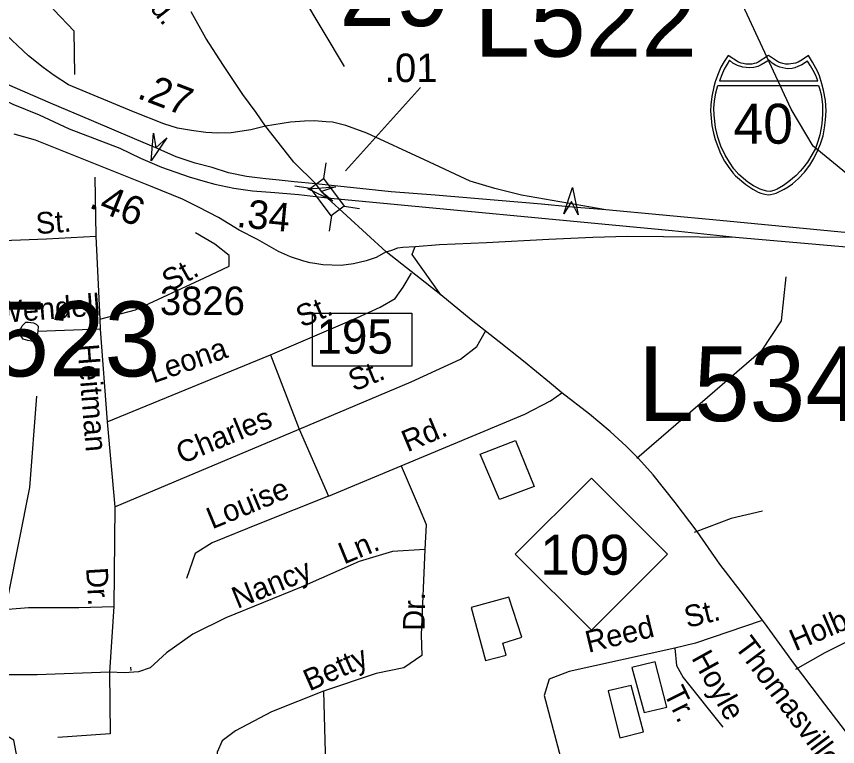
# Model space of a CAD drawing. Extents: x 1553981 to 1780076, y 812965 to 996873.
# Drawn here: x 1634453.2 to 1634902.9, y 846130.3 to 846530.3 of the extents above; entities that cross this region are included whole.
import ezdxf

# ---------------------------------------------------------------- set-up
doc = ezdxf.new("R2010")
doc.units = 0
for name, color, linetype in [('Exist Civil Correctional or Penal Institution CELL', 7, 'Continuous'), ('Exist Civil NCDOT Division Office Label', 7, 'Continuous'), ('Exist Cultural Church with Cemetery CELL', 7, 'Continuous'), ('Exist Cultural Warehouse Building Footprint', 7, 'Continuous'), ('Exist Geographical Mountain Summit Label', 7, 'Continuous'), ('Exist Hydrographic Creek Single Shore', 7, 'Continuous'), ('Exist Road Non-System Type 51 Label', 7, 'Continuous'), ('Exist Road Primary Interstate Divided Center Attributed', 7, 'Continuous'), ('Exist Road Primary Interstate Ramp 1 Lane Attributed', 7, 'Continuous'), ('Exist Road Primary Interstate Service Attributed', 7, 'Continuous'), ('Exist Road Primary Interstate Shield CELL', 7, 'Continuous'), ('Exist Road Primary Interstate Structure Cantilever Sign Number Label', 7, 'Continuous'), ('Exist Road Primary NC Attributed', 7, 'Continuous'), ('Exist Road Primary NC Label', 7, 'Continuous'), ('Exist Road Primary NC Service Mileage Hundredths English Label', 7, 'Continuous'), ('Exist Road Primary NC Shield Number Label', 7, 'Continuous'), ('Exist Road Primary NC Structure Standard Bridge CELL', 7, 'Continuous'), ('Exist Road Secondary Structure Standard Bridge Attributed CELL', 7, 'Continuous'), ('Exist Road Secondary Structure Standard Bridge Number Label', 7, 'Continuous'), ('Exist Road Secondary Type 51 Attributed', 7, 'Continuous'), ('Exist Road Secondary Type 51 Number Label', 7, 'Continuous'), ('Map Preparation Border Antique Large Shape', 7, 'Continuous'), ('Map Preparation Border County Name Lower Right Label', 7, 'Continuous'), ('Map Preparation Border Division and District Label', 7, 'Continuous')]:
    doc.layers.add(name, color=color, linetype=linetype)

msp = doc.modelspace()

# ---------------------------------------------------------------- linework, layer by layer
at = {"layer": 'Exist Civil Correctional or Penal Institution CELL'}
msp.add_lwpolyline([(1634615.3, 846367.85), (1634669.67, 846367.85), (1634669.67, 846338.69), (1634615.3, 846338.69)], close=True, dxfattribs=at)
at = {"layer": 'Exist Cultural Church with Cemetery CELL'}
for points in [[(1634535.67, 846463.73), (1634527.02, 846451.19), (1634528.24, 846466.38), (1634529.57, 846458.37)], [(1634752.88, 846422.12), (1634757.64, 846436.6), (1634760.75, 846421.68), (1634757.21, 846428.99)]]:
    msp.add_lwpolyline(points, close=True, dxfattribs=at)
at = {"layer": 'Exist Cultural Warehouse Building Footprint'}
for points in [[(1634726.5, 846297.94), (1634736.65, 846272.88), (1634717.7, 846265.77), (1634707.21, 846290.49)], [(1634702.14, 846206.5), (1634710.13, 846177.55), (1634721.43, 846180.43), (1634719.48, 846186.91), (1634729.88, 846190.25), (1634722.78, 846212.26)], [(1634790.11, 846173.66), (1634796.88, 846148.94), (1634809.4, 846151.98), (1634802.97, 846176.7)], [(1634777.25, 846160.79), (1634783.68, 846135.05), (1634796.54, 846138.44), (1634789.77, 846163.84)]]:
    msp.add_lwpolyline(points, close=True, dxfattribs=at)
at = {"layer": 'Exist Hydrographic Creek Single Shore'}
for points in [[(1635251.23, 845900.49), (1635241.98, 845905.61), (1635222.36, 845924.47), (1635148.73, 846037.17), (1635133.36, 846064.15), (1635107.11, 846126.24), (1635100.35, 846173.96), (1635092.23, 846190.95), (1635059.23, 846226.51), (1635014.48, 846310.71), (1634938.4, 846360.17), (1634946.3, 846370.23), (1634946.3, 846412.62), (1634889.57, 846459.33), (1634877.36, 846479.45), (1634841.23, 846557.55), (1634830.22, 846595.11), (1634817.1, 846624.51), (1634780.1, 846674.92), (1634763.85, 846710.53), (1634754.1, 846766.12)], [(1634456.59, 846108.66), (1634451.72, 846133.8), (1634448.6, 846135.9), (1634447.73, 846148.65), (1634443.6, 846160.22), (1634442.84, 846184.03), (1634460.59, 846272.3), (1634464.35, 846322.29)]]:
    msp.add_lwpolyline(points, dxfattribs=at)
at = {"layer": 'Exist Road Primary Interstate Divided Center Attributed'}
for points in [[(1635310.9, 846514.99), (1635297.81, 846505.94), (1635206.93, 846450.34), (1635199, 846446.14), (1635187.26, 846439.53), (1635181.99, 846437), (1635165.26, 846429.66), (1635149.65, 846423.53), (1635130.45, 846416.93), (1635118.31, 846413.99), (1635103.77, 846410.13), (1635090.7, 846407.43), (1635083.37, 846406.49), (1635071.95, 846405.37), (1635060.1, 846403.72), (1635032.42, 846402.32), (1634978.81, 846405.12), (1634940.93, 846408.59), (1634838.36, 846418.57), (1634775.88, 846424.31)], [(1634617.18, 846438.56), (1634605.25, 846439.73), (1634597.1, 846440.6), (1634589.71, 846441.31), (1634583.63, 846442.13), (1634579.27, 846442.71), (1634569.36, 846444.65), (1634560.42, 846447.59), (1634551.11, 846449.92), (1634540.63, 846453.41), (1634529.57, 846458.37), (1634517.93, 846463.32), (1634494.36, 846473.22), (1634471.94, 846482.83), (1634448.37, 846493.02), (1634430.55, 846500.64), (1634404.55, 846511.95)], [(1634397.6, 846506.78), (1634417.39, 846497.59), (1634432.82, 846490.95), (1634451.23, 846482.23), (1634465.66, 846476.41), (1634482.13, 846468.77), (1634509.78, 846458.07), (1634521.17, 846452.72), (1634532.58, 846447.66), (1634547.88, 846442.39), (1634556.65, 846439.8), (1634561.82, 846438.51), (1634572.34, 846436.18), (1634582.52, 846434.73), (1634594.77, 846433.9), (1634607.87, 846432.74), (1634623.29, 846430.99)], [(1634847.02, 846409.33), (1634974.81, 846398.32), (1635004.81, 846395.26), (1635020.95, 846394.19), (1635051.03, 846394.59), (1635057.62, 846395.16), (1635069.56, 846395.12), (1635087.17, 846396.16), (1635103.77, 846398.66), (1635118.98, 846401.86), (1635136.98, 846406.26), (1635163.19, 846414.79), (1635185.2, 846424.03), (1635207.67, 846435.53), (1635224.87, 846445.4), (1635279.89, 846479.71), (1635322.1, 846505.59)], [(1634775.88, 846424.31), (1634755.48, 846426.05), (1634740.82, 846427.53), (1634682.48, 846432.46), (1634658.47, 846434.31), (1634617.18, 846438.56)], [(1634623.29, 846430.99), (1634812.21, 846412.96), (1634847.02, 846409.33)]]:
    msp.add_lwpolyline(points, dxfattribs=at)
at = {"layer": 'Exist Road Primary Interstate Ramp 1 Lane Attributed'}
for points in [[(1634775.88, 846424.31), (1634729.86, 846432.48), (1634715.22, 846436.14), (1634701.65, 846440.12), (1634676.64, 846451.73), (1634645.01, 846466.29), (1634633.59, 846470.6), (1634626.28, 846472.33), (1634622.77, 846472.65), (1634616.2, 846473.18), (1634610.98, 846472.97), (1634603.23, 846472.43), (1634589.61, 846470.21)], [(1634671.56, 846404.33), (1634684.92, 846405.34), (1634710.64, 846406.42), (1634744.83, 846408.25), (1634768.79, 846409.43), (1634787.74, 846409.97), (1634847.02, 846409.33)], [(1634655.67, 846401.36), (1634658.74, 846402.33), (1634662.08, 846403.51), (1634664.77, 846403.94), (1634671.56, 846404.33)], [(1634685.55, 846377.78), (1634669.94, 846399.96), (1634670.69, 846401.9), (1634671.56, 846404.33)]]:
    msp.add_lwpolyline(points, dxfattribs=at)
at = {"layer": 'Exist Road Primary Interstate Service Attributed'}
for points in [[(1634589.61, 846470.21), (1634581.67, 846468.28), (1634570.82, 846466.51), (1634563.44, 846466.35), (1634556.92, 846466.67), (1634549.07, 846467.85), (1634541.34, 846469.07), (1634533.95, 846471.57), (1634517.37, 846477.97), (1634481.76, 846492.89), (1634473.95, 846497.95), (1634467.81, 846502.26), (1634459.84, 846508.82), (1634444.61, 846522.93), (1634432.17, 846532.73)], [(1634655.67, 846401.36), (1634650.23, 846398.24), (1634644.77, 846396.51), (1634637.82, 846394.74), (1634630.98, 846393.82), (1634620.94, 846394.25), (1634616.64, 846395.03), (1634614.1, 846395.38), (1634610.54, 846396.25), (1634603.22, 846398.69), (1634596.71, 846401.54), (1634585.14, 846408.09), (1634575.18, 846413.29), (1634563.92, 846420.1), (1634552.99, 846425.91), (1634544.19, 846430.16), (1634526.66, 846437.33), (1634485.63, 846453.8), (1634463.75, 846462.47), (1634452.08, 846465.85)]]:
    msp.add_lwpolyline(points, dxfattribs=at)
at = {"layer": 'Exist Road Primary Interstate Shield CELL'}
for points in [[(1634865, 846432.63), (1634866.18, 846432.74), (1634867.78, 846433.05), (1634869.32, 846433.56), (1634871.09, 846434.34), (1634873.69, 846435.78), (1634875.79, 846437.01), (1634878.2, 846438.64), (1634881.47, 846441.6), (1634884.72, 846445.03), (1634887.6, 846448.91), (1634889.88, 846452.53), (1634891.89, 846456.68), (1634893.57, 846460.54), (1634894.9, 846464.96), (1634895.78, 846469.24), (1634896.23, 846473.7), (1634896.53, 846478.65), (1634896.19, 846484.21), (1634895.22, 846489.91), (1634894.31, 846493.45), (1634892.94, 846497.7), (1634891.81, 846500.4), (1634889.21, 846505.21), (1634886.86, 846508.91), (1634883.46, 846506.51), (1634881.24, 846505.33), (1634879.88, 846504.72), (1634878.49, 846504.45), (1634875.93, 846504.14), (1634874.32, 846504.21), (1634872.82, 846504.55), (1634871.56, 846504.83), (1634870.53, 846505.33), (1634865, 846508.91), (1634859.46, 846505.33), (1634858.3, 846504.8), (1634857.12, 846504.55), (1634855.97, 846504.23), (1634854.08, 846504.14), (1634852.63, 846504.19), (1634851.15, 846504.45), (1634849.98, 846504.7), (1634848.66, 846505.33), (1634843.02, 846508.91), (1634840.81, 846505.69), (1634839, 846502.52), (1634837.08, 846498.03), (1634835.89, 846494.55), (1634835.04, 846491.69), (1634833.99, 846486.45), (1634833.45, 846481.88), (1634833.36, 846478.65), (1634833.95, 846470.58), (1634834.83, 846466.29), (1634835.74, 846462.81), (1634838.72, 846455.31), (1634840.96, 846451.11), (1634842.89, 846448.09), (1634845.58, 846444.69), (1634847.05, 846443.07), (1634852.65, 846438.17), (1634856.39, 846435.62), (1634859.38, 846434.01), (1634860.78, 846433.47), (1634862.98, 846432.86)], [(1634843.7, 846506.32), (1634842.32, 846504.2), (1634840.74, 846501.35), (1634839.47, 846498.39), (1634838.17, 846495.12), (1634892.12, 846495.1), (1634890.86, 846497.9), (1634889.52, 846500.72), (1634888.11, 846503.29), (1634886.4, 846505.77), (1634883.37, 846503.87), (1634881.17, 846502.83), (1634879.4, 846502.22), (1634877.9, 846501.88), (1634875.57, 846501.69), (1634874.53, 846501.76), (1634871.29, 846502.49), (1634869.1, 846503.39), (1634867.01, 846504.78), (1634865.32, 846506.37), (1634861.05, 846503.78), (1634859.15, 846502.95), (1634856.97, 846502.39), (1634854.58, 846502.09), (1634850.91, 846502.49), (1634848.02, 846503.49), (1634845.54, 846504.78)], [(1634892.44, 846492.43), (1634893.02, 846490.91), (1634893.81, 846487.53), (1634894.23, 846484.93), (1634894.66, 846481.93), (1634894.51, 846476.79), (1634894.26, 846471.46), (1634893.77, 846468.31), (1634893.12, 846465.44), (1634892.22, 846462.26), (1634890.78, 846458.03), (1634888.79, 846454.45), (1634886.31, 846450.47), (1634883.62, 846446.99), (1634882.45, 846445.54), (1634880.24, 846443.21), (1634876.21, 846439.98), (1634873.27, 846437.78), (1634869.75, 846435.7), (1634867.96, 846434.9), (1634865.88, 846434.47), (1634864.17, 846434.59), (1634862.09, 846435.14), (1634860.41, 846435.6), (1634856.73, 846437.59), (1634853.75, 846439.58), (1634848.78, 846443.66), (1634846.09, 846446.8), (1634843.59, 846450.47), (1634841.35, 846454.23), (1634838.97, 846459.19), (1634837.29, 846464.18), (1634836.06, 846469.56), (1634835.24, 846476.14), (1634835.15, 846480.15), (1634835.39, 846484.01), (1634835.76, 846486.03), (1634836.25, 846488.54), (1634837.23, 846492.41)]]:
    msp.add_lwpolyline(points, close=True, dxfattribs=at)
at = {"layer": 'Exist Road Primary NC Attributed'}
for points in [[(1634623.29, 846430.99), (1634620.28, 846434.49), (1634617.18, 846438.56)], [(1634655.67, 846401.36), (1634623.29, 846430.99)], [(1634685.55, 846377.78), (1634655.67, 846401.36)], [(1634909.53, 846135.59), (1634893.49, 846156.7), (1634879.22, 846175.54), (1634872.55, 846184.7), (1634862.91, 846198.16), (1634850.04, 846215.17), (1634838.33, 846230.26), (1634825.97, 846248.23), (1634813.91, 846263.95), (1634801.8, 846279.24), (1634793.94, 846288.18), (1634787.11, 846294.97), (1634778.41, 846302.99), (1634767.02, 846312.42), (1634751.91, 846324.18), (1634745.05, 846329.72), (1634730.97, 846341.4), (1634717.59, 846352.04), (1634702.18, 846364.11), (1634685.55, 846377.78)]]:
    msp.add_lwpolyline(points, dxfattribs=at)
at = {"layer": 'Exist Road Primary NC Service Mileage Hundredths English Label'}
msp.add_line((1634633.39, 846445.79), (1634674.48, 846491.34), dxfattribs=at)
at = {"layer": 'Exist Road Primary NC Structure Standard Bridge CELL'}
for p, q in [((1634622.56, 846450.08), (1634621.33, 846441.54)), ((1634605.74, 846437.47), (1634614.27, 846436.25)), ((1634632.63, 846426.4), (1634641.16, 846425.18)), ((1634625.72, 846421.23), (1634624.5, 846412.69))]:
    msp.add_line(p, q, dxfattribs=at)
msp.add_lwpolyline([(1634621.33, 846441.54), (1634632.66, 846426.42), (1634625.6, 846421.13), (1634614.27, 846436.25)], close=True, dxfattribs=at)
at = {"layer": 'Exist Road Secondary Structure Standard Bridge Attributed CELL'}
msp.add_lwpolyline([(1634626.5, 846429.27), (1634612.8, 846435.95), (1634628, 846437.01), (1634620.28, 846434.49)], close=True, dxfattribs=at)
at = {"layer": 'Exist Road Secondary Type 51 Attributed'}
for points in [[(1634589.61, 846470.21), (1634584.52, 846477.71), (1634577.22, 846487.46), (1634566.56, 846503.5), (1634556.92, 846518.36), (1634548.96, 846532.84)], [(1634617.18, 846438.56), (1634605.18, 846450.41), (1634590.53, 846469.18), (1634589.61, 846470.21)]]:
    msp.add_lwpolyline(points, dxfattribs=at)
at = {"layer": 'Map Preparation Border County Name Lower Right Label'}
msp.add_line((1634515.75, 846173.84), (1634515.84, 846171.96), dxfattribs=at)
for points in [[(1634585.87, 846581.24), (1634632.68, 846502.83)], [(1634485.19, 846498.44), (1634484.82, 846522.3), (1634473.64, 846533.86), (1634468.78, 846543.09), (1634455.68, 846552.44)], [(1634496.13, 846442.22), (1634496.79, 846409.87)], [(1634354.14, 846406.13), (1634436.09, 846407.13), (1634469.7, 846408.5), (1634496.79, 846409.87)], [(1634496.79, 846409.87), (1634498.87, 846364.4)], [(1634498.87, 846364.4), (1634518.39, 846369.54), (1634556.15, 846387.16), (1634569.78, 846393.54), (1634569.78, 846399.37), (1634561.9, 846405.54), (1634551.28, 846411.71)], [(1634592.37, 846344.95), (1634639.65, 846365.18), (1634652.33, 846371.01), (1634660.55, 846375.81), (1634665, 846381.98), (1634669.57, 846389.6)], [(1634874.5, 846387.73), (1634871.99, 846363.57), (1634861.03, 846346.96), (1634792.95, 846288.22)], [(1634498.87, 846364.4), (1634499.14, 846358.91)], [(1634465.01, 846357.67), (1634464.47, 846354.68), (1634463.45, 846353.43), (1634461.43, 846352.47), (1634459.43, 846352.76), (1634456.95, 846353.53), (1634455.73, 846355.31), (1634455.27, 846357.07), (1634455.53, 846358.81), (1634456.32, 846360.8), (1634457.34, 846361.78), (1634458.36, 846362.76), (1634459.61, 846362.76), (1634461.08, 846362.73), (1634462.58, 846362.45), (1634464.06, 846361.67), (1634464.82, 846360.93), (1634465.07, 846360.67), (1634465.01, 846357.67)], [(1634499.14, 846358.91), (1634465.01, 846357.67)], [(1634499.14, 846358.91), (1634502.96, 846308.27)], [(1634608.13, 846304.16), (1634669.34, 846330.22), (1634696.41, 846342.56), (1634705.32, 846349.42), (1634710.11, 846357.99)], [(1634502.96, 846308.27), (1634592.37, 846344.95)], [(1634592.37, 846344.95), (1634608.13, 846304.16)], [(1634663.9, 846284.14), (1634731.66, 846312.46), (1634745.71, 846319.66), (1634751.91, 846324.18)], [(1634502.96, 846308.27), (1634507.07, 846261.64)], [(1634507.07, 846261.64), (1634608.13, 846304.16)], [(1634608.13, 846304.16), (1634624.12, 846267.56)], [(1634624.12, 846267.56), (1634663.9, 846284.14)], [(1634663.9, 846284.14), (1634673.83, 846261.17), (1634677.6, 846251.92), (1634676.91, 846238.2)], [(1634624.12, 846267.56), (1634586.45, 846252.57), (1634560.41, 846241.95), (1634551.16, 846236.12), (1634546.36, 846222.4)], [(1634507.07, 846261.64), (1634506.62, 846206.98)], [(1634861.7, 846259.31), (1634844.63, 846255.33), (1634824.28, 846247.6)], [(1634676.91, 846238.2), (1634659.1, 846237.18), (1634640.94, 846231.69), (1634609.08, 846217.63), (1634567.97, 846200.83), (1634549.81, 846191.92), (1634535.42, 846181.64), (1634526.52, 846173.41), (1634520.01, 846171.35), (1634512.47, 846170.66), (1634504.25, 846171.01)], [(1634676.91, 846238.2), (1634674.86, 846191.58), (1634675.2, 846180.26), (1634665.27, 846173.41), (1634650.19, 846170.32), (1634621.41, 846160.72)], [(1634346.64, 846203.86), (1634403.26, 846205.42), (1634439.61, 846204.9), (1634459.87, 846206.46), (1634487.4, 846206.46), (1634506.62, 846206.98)], [(1634506.62, 846206.98), (1634504.25, 846171.01)], [(1634861.08, 846199.29), (1634824.98, 846187.06), (1634813.68, 846184.24)], [(1634923.11, 846194.33), (1634909, 846188.29), (1634895.91, 846181.75), (1634879.73, 846172.6)], [(1634813.68, 846184.24), (1634755.81, 846171.53), (1634744.99, 846167.29), (1634742.16, 846158.34), (1634751.1, 846124.44), (1634765.69, 846066.53)], [(1634813.68, 846184.24), (1634814.62, 846174.82), (1634818.39, 846168.23), (1634840.03, 846140.92)], [(1634504.25, 846171.01), (1634464.54, 846169.56), (1634391.83, 846169.56), (1634346.64, 846170.6)], [(1634504.25, 846171.01), (1634504.54, 846137.33), (1634475.97, 846135.25)], [(1634621.41, 846160.72), (1634592.97, 846149.29), (1634573.1, 846139), (1634565.91, 846133.52), (1634563.17, 846127.34), (1634563.17, 846107.12)], [(1634621.41, 846160.72), (1634622.78, 846106.77)]]:
    msp.add_lwpolyline(points, dxfattribs=at)
at = {"layer": 'Map Preparation Border Division and District Label'}
msp.add_lwpolyline([(1634726.4, 846235.69), (1634768.03, 846277.31), (1634809.65, 846235.69), (1634768.03, 846194.06)], close=True, dxfattribs=at)

# ---------------------------------------------------------------- texts
at = {"layer": 'Exist Civil Correctional or Penal Institution CELL'}
msp.add_text('195', height=18.75, dxfattribs=at).set_placement((1634617.5, 846345.55))
at = {"layer": 'Exist Civil NCDOT Division Office Label'}
for s, rotation, p in [('.27', 338.9145, (1634518.75, 846485.81)), ('.46', 338.1208, (1634492.39, 846425.83)), ('.34', 354.5179, (1634573.4, 846415.03))]:
    msp.add_text(s, height=15.625, rotation=rotation, dxfattribs=at).set_placement(p)
at = {"layer": 'Exist Geographical Mountain Summit Label'}
msp.add_text('40', height=21.875, dxfattribs=at).set_placement((1634845.89, 846460.6))
at = {"layer": 'Exist Road Non-System Type 51 Label'}
for s, rotation, p in [('St.', 4.466, (1634464.27, 846410.99)), ('St.', 29.1967, (1634537.15, 846379.28)), ('Wendell', 4.556, (1634442.24, 846362.14)), ('St.', 23.094, (1634609.47, 846359.74)), ('Leona', 19.2252, (1634528.12, 846329.19)), ('Heitman', 274.5813, (1634486.54, 846350.47)), ('St.', 22.1014, (1634637.98, 846324.72)), ('Charles', 22.5302, (1634543.76, 846284.93)), ('Rd.', 22.8341, (1634667.33, 846291.48)), ('Louise', 22.5141, (1634560.42, 846249.26)), ('Ln.', 22.1778, (1634632.57, 846230.04)), ('Nancy', 22.2454, (1634574.22, 846205.7)), ('Dr.', 273.4821, (1634491.36, 846228.18)), ('Holbrook', 23.1883, (1634879.74, 846182.44)), ('Dr.', 89.541, (1634676.76, 846193.73)), ('St.', 13.7629, (1634820.54, 846195.24)), ('Reed', 13.7767, (1634766.38, 846181.66)), ('Betty', 23.8206, (1634613.67, 846160.5)), ('Hoyle', 299.0927, (1634822.57, 846178.9)), ('Tr.', 296.2746, (1634807.41, 846159.82))]:
    msp.add_text(s, height=11.875, rotation=rotation, dxfattribs=at).set_placement(p)
at = {"layer": 'Exist Road Primary Interstate Structure Cantilever Sign Number Label'}
for s, p in [('L522', (1634703.93, 846508.29)), ('L523', (1634409.99, 846333.13)), ('L534', (1634793.66, 846308.63))]:
    msp.add_text(s, height=41.01, dxfattribs=at).set_placement(p)
at = {"layer": 'Exist Road Primary NC Label'}
msp.add_text('Thomasville', height=11.875, rotation=306.7328, dxfattribs=at).set_placement((1634846.04, 846185.14))
at = {"layer": 'Exist Road Primary NC Service Mileage Hundredths English Label'}
msp.add_text('.01', height=15.625, rotation=0.1815, dxfattribs=at).set_placement((1634654.74, 846494.31))
at = {"layer": 'Exist Road Primary NC Shield Number Label'}
msp.add_text('109', height=21.875, dxfattribs=at).set_placement((1634740.04, 846224.48))
at = {"layer": 'Exist Road Secondary Structure Standard Bridge Number Label'}
msp.add_text('29', height=41.01, dxfattribs=at).set_placement((1634630.04, 846525.05))
at = {"layer": 'Exist Road Secondary Type 51 Number Label'}
msp.add_text('3826', height=15.625, dxfattribs=at).set_placement((1634531.84, 846366.72))
at = {"layer": 'Map Preparation Border Antique Large Shape'}
msp.add_text('Rd.', height=11.875, rotation=308.1175, dxfattribs=at).set_placement((1634518.78, 846544.02))

doc.saveas('drawing.dxf')
